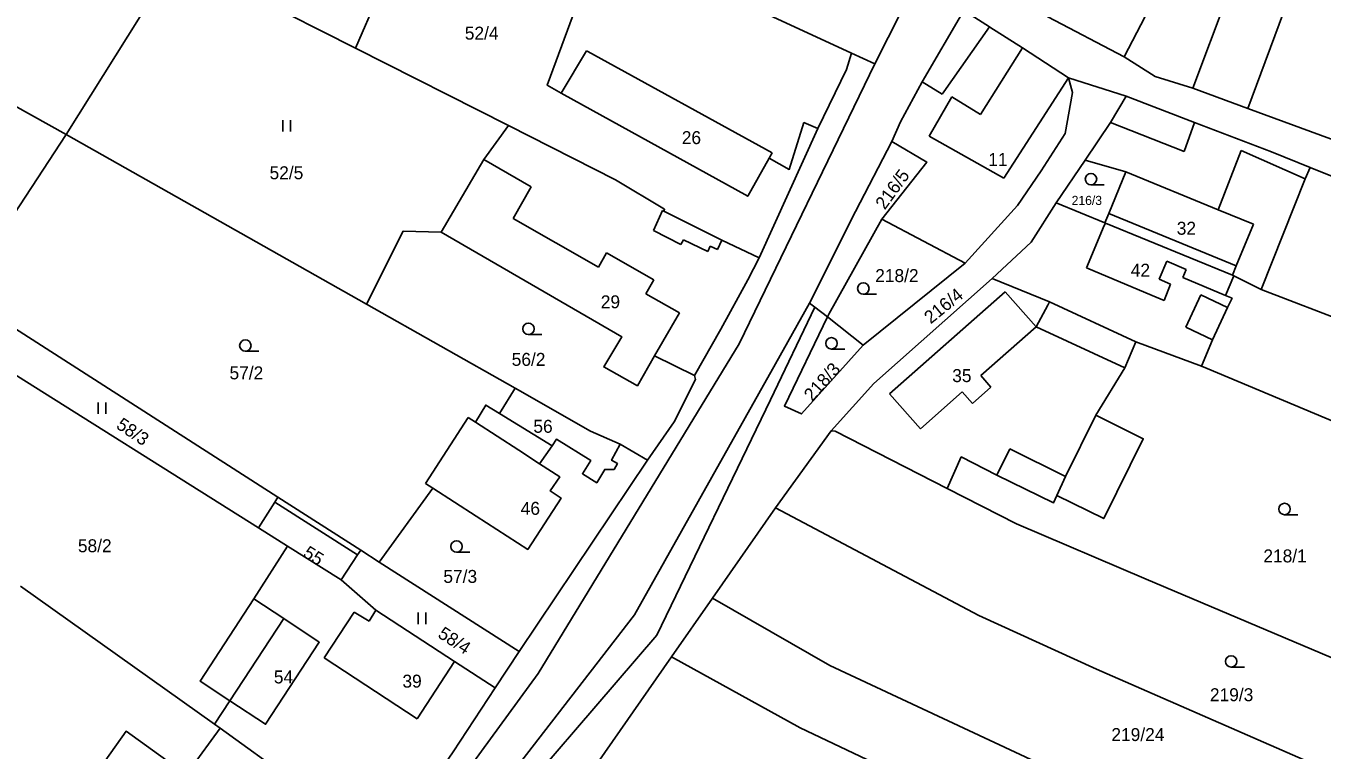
# Model space of a CAD drawing. Extents: x -746176 to -739709, y -1128407 to -1124482.
# Drawn here: x -743087.7 to -742917.8, y -1127669.6 to -1127574.6 of the extents above; entities that cross this region are included whole.
import ezdxf

# ---------------------------------------------------------------- set-up
doc = ezdxf.new("R2010")
doc.units = 0
for name, color, linetype in [('Hranice parcel', 7, 'Continuous'), ('Parcelní čísla', 7, 'Continuous'), ('Vnitřní kresba', 7, 'Continuous'), ('Značky kultur', 7, 'Continuous')]:
    doc.layers.add(name, color=color, linetype=linetype)

msp = doc.modelspace()

# ---------------------------------------------------------------- linework, layer by layer
at = {"layer": 'Hranice parcel'}
for p, q in [((-743082.43, -1127588.87), (-743239.89, -1127501.37)), ((-743029.41, -1127542.64), (-743044.5, -1127577.53)), ((-743082.43, -1127588.87), (-743067.95, -1127565.66)), ((-743067.95, -1127565.66), (-743044.5, -1127577.53)), ((-742979.47, -1127578.16), (-743001.38, -1127568.05)), ((-743044.5, -1127577.53), (-743024.44, -1127587.67)), ((-742943.48, -1127583.82), (-742951.01, -1127581.4)), ((-742985.72, -1127587.27), (-742983.9, -1127588.07)), ((-743096.19, -1127609.82), (-743082.43, -1127588.87)), ((-743082.43, -1127588.87), (-743043.08, -1127611.1)), ((-742991.6, -1127605.04), (-742983.9, -1127588.07)), ((-742952.62, -1127597.82), (-742948.85, -1127592.21)), ((-742919.33, -1127593.19), (-742889.07, -1127605.41)), ((-742946.24, -1127600.44), (-742952.62, -1127597.82)), ((-742982.46, -1127612.4), (-742975.48, -1127599.94)), ((-742975.48, -1127599.94), (-742964.56, -1127605.74)), ((-742964.56, -1127605.74), (-742977.94, -1127616.47)), ((-742925.74, -1127609.17), (-742929.36, -1127607.37)), ((-742892.31, -1127622.04), (-742925.74, -1127609.17)), ((-743096.19, -1127609.82), (-743054.68, -1127636.42)), ((-743043.08, -1127611.1), (-743023.57, -1127622.12)), ((-742982.64, -1127612.78), (-742984.29, -1127611.5)), ((-742982.64, -1127612.78), (-742982.46, -1127612.4)), ((-742977.94, -1127616.47), (-742982.64, -1127612.78)), ((-743057.24, -1127640.46), (-743099.02, -1127614.17)), ((-742933.59, -1127619.25), (-742942.21, -1127616.04)), ((-743023.57, -1127622.12), (-743025.65, -1127625.44)), ((-743029.73, -1127625.98), (-743035.35, -1127634.62)), ((-743018.73, -1127629.7), (-743025.65, -1127625.44)), ((-742989.43, -1127637.82), (-742982.16, -1127627.73)), ((-743009.79, -1127629.49), (-743006.21, -1127631.58)), ((-743006.21, -1127631.58), (-743023.07, -1127656.68)), ((-743035.35, -1127634.62), (-743034.37, -1127635.25)), ((-743043.83, -1127643.37), (-743054.68, -1127636.42)), ((-743041.39, -1127644.94), (-743034.37, -1127635.25)), ((-742997.69, -1127649.67), (-742989.43, -1127637.82)), ((-743057.24, -1127640.46), (-743053.43, -1127642.86)), ((-743053.43, -1127642.86), (-743057.84, -1127649.75)), ((-743046.41, -1127647.29), (-743053.43, -1127642.86)), ((-743043.83, -1127643.37), (-743041.39, -1127644.94)), ((-743041.39, -1127644.94), (-743023.07, -1127656.68)), ((-743062.98, -1127666.21), (-743088.43, -1127648.09)), ((-743003.07, -1127657.38), (-742997.69, -1127649.67)), ((-743023.07, -1127656.68), (-743026.2, -1127661.44)), ((-743013.81, -1127672.8), (-743003.07, -1127657.38)), ((-743060.97, -1127663.13), (-743062.98, -1127666.21)), ((-743062.24, -1127666.73), (-743062.98, -1127666.21)), ((-743045.29, -1127678.95), (-743062.24, -1127666.73))]:
    msp.add_line(p, q, dxfattribs=at)
for points in [[(-742927.53, -1127585.44), (-742922.25, -1127571.32), (-742918.6, -1127561.55)], [(-743009.74, -1127564.2), (-743012.24, -1127563.05), (-743019.38, -1127582.4), (-743017.56, -1127583.41), (-742993.08, -1127596.96), (-742990.26, -1127591.96)], [(-742967.51, -1127562.65), (-742971.19, -1127569.17), (-742976.43, -1127579.56), (-742979.47, -1127578.16)], [(-742927.53, -1127585.44), (-742934.7, -1127582.76), (-742939.64, -1127581.23), (-742943.72, -1127578.66), (-742953.72, -1127573.43), (-742957.84, -1127570.04), (-742958.76, -1127567.42), (-742958.43, -1127564.08)], [(-742964.75, -1127572.6), (-742970.21, -1127581.92), (-742973.05, -1127587.2), (-742974.2, -1127589.77)], [(-742951.01, -1127581.4), (-742957.06, -1127577.5), (-742961.32, -1127574.78), (-742961.39, -1127574.71), (-742964.75, -1127572.6)], [(-742983.9, -1127588.07), (-742980.12, -1127580.33), (-742979.47, -1127578.16)], [(-742964.56, -1127605.74), (-742957.73, -1127598.16), (-742954.62, -1127593.61), (-742951.47, -1127588.73), (-742950.51, -1127583.33), (-742951.01, -1127581.4)], [(-742948.85, -1127592.21), (-742945.53, -1127587.26), (-742943.48, -1127583.82)], [(-742943.48, -1127583.82), (-742934.51, -1127587.27), (-742924.42, -1127591.13), (-742919.33, -1127593.19)], [(-742885.79, -1127600.64), (-742896.8, -1127596.74), (-742927.53, -1127585.44)], [(-742990.26, -1127591.96), (-742987.63, -1127593.44), (-742985.72, -1127587.27)], [(-743024.44, -1127587.67), (-743027.7, -1127592.11), (-743033.28, -1127601.65)], [(-743024.44, -1127587.67), (-743010.42, -1127594.79), (-743003.98, -1127598.66), (-743004.09, -1127598.89), (-742996.47, -1127602.7), (-742991.6, -1127605.04)], [(-742984.29, -1127611.5), (-742984.97, -1127610.98), (-742978.95, -1127598.97), (-742974.2, -1127589.77)], [(-742974.2, -1127589.77), (-742969.61, -1127592.47), (-742975.48, -1127599.94)], [(-742948.85, -1127592.21), (-742943.5, -1127593.76), (-742945.74, -1127599.22), (-742946.24, -1127600.44)], [(-742925.74, -1127609.17), (-742920.01, -1127594.66), (-742919.33, -1127593.19)], [(-742961.05, -1127607.72), (-742955.92, -1127602.99), (-742952.62, -1127597.82)], [(-742946.24, -1127600.44), (-742946.19, -1127600.46), (-742929.52, -1127607.31), (-742929.36, -1127607.37)], [(-743043.08, -1127611.1), (-743038.28, -1127601.54), (-743033.28, -1127601.65)], [(-743033.28, -1127601.65), (-743009.6, -1127615.39), (-743011.96, -1127619.34), (-743007.55, -1127621.8), (-743005.29, -1127617.87), (-743000.05, -1127620.45)], [(-742991.6, -1127605.04), (-742993.07, -1127607.9), (-742996.62, -1127614.4), (-743000.05, -1127620.45)], [(-742982.16, -1127627.73), (-742976.55, -1127621.53), (-742961.05, -1127607.72)], [(-742942.21, -1127616.04), (-742953.51, -1127610.79), (-742961.05, -1127607.72)], [(-742929.36, -1127607.37), (-742930.45, -1127609.97), (-742929.58, -1127610.33), (-742930.16, -1127611.56), (-742932.13, -1127615.77), (-742933.59, -1127619.25)], [(-742984.29, -1127611.5), (-742990.11, -1127623.65), (-743005.02, -1127654.54), (-743028.72, -1127682.17), (-743035.1, -1127691.53)], [(-742977.94, -1127616.47), (-742986.05, -1127625.51), (-742988.28, -1127624.48), (-742982.64, -1127612.78)], [(-742942.21, -1127616.04), (-742943.64, -1127619.44), (-742947.46, -1127625.69), (-742941.23, -1127628.77), (-742946.4, -1127639.24), (-742952.54, -1127636.21), (-742953.01, -1127637.17), (-742960.41, -1127633.52), (-742965.09, -1127631.14), (-742966.93, -1127635.29)], [(-742933.59, -1127619.25), (-742932.84, -1127619.53), (-742895.2, -1127635.33)], [(-743000.05, -1127620.45), (-742999.93, -1127620.98), (-743002.72, -1127626.56), (-743006.21, -1127631.58)], [(-743009.79, -1127629.49), (-743013.72, -1127627.78), (-743023.57, -1127622.12)], [(-743025.65, -1127625.44), (-743027.43, -1127624.34), (-743028.79, -1127626.59), (-743029.73, -1127625.98)], [(-742966.93, -1127635.29), (-742981.61, -1127627.78), (-742982.16, -1127627.73)], [(-743034.37, -1127635.25), (-743028.68, -1127638.9), (-743021.92, -1127643.29), (-743017.55, -1127636.55), (-743018.97, -1127635.6), (-743017.73, -1127633.76), (-743020.38, -1127632.04), (-743018.73, -1127629.7)], [(-743018.73, -1127629.7), (-743018.16, -1127628.82), (-743013.67, -1127631.63), (-743014.75, -1127633.35), (-743012.87, -1127634.54), (-743011.82, -1127632.78), (-743010.61, -1127632.81), (-743010.16, -1127632.03), (-743010.94, -1127631.59), (-743009.79, -1127629.49)], [(-743054.68, -1127636.42), (-743055.09, -1127637.08), (-743057.24, -1127640.46)], [(-742966.93, -1127635.29), (-742957.86, -1127639.93), (-742940.86, -1127647.2), (-742894.92, -1127666.66), (-742890.34, -1127668.53)], [(-742989.43, -1127637.82), (-742962.79, -1127651.94), (-742947.37, -1127659.01), (-742888.66, -1127684.65), (-742875.08, -1127689.31), (-742869.86, -1127690.69)], [(-743046.41, -1127647.29), (-743044.24, -1127643.99), (-743043.83, -1127643.37)], [(-743026.2, -1127661.44), (-743031.54, -1127657.97), (-743041.85, -1127651.26), (-743046.41, -1127647.29)], [(-743057.84, -1127649.75), (-743064.89, -1127660.55), (-743060.97, -1127663.13)], [(-743057.84, -1127649.75), (-743053.93, -1127652.35), (-743049.27, -1127655.45), (-743056.31, -1127666.21), (-743060.97, -1127663.13)], [(-742884.93, -1127701.69), (-742931.01, -1127682.52), (-742982.33, -1127658.51), (-742997.69, -1127649.67)], [(-742892.82, -1127707.45), (-742959.07, -1127679.57), (-742986.2, -1127666.67), (-743003.07, -1127657.38)], [(-743026.2, -1127661.44), (-743031.72, -1127669.85), (-743034.56, -1127673.98), (-743037.58, -1127678), (-743040.96, -1127682.5)], [(-743050.26, -1127695.79), (-743074.95, -1127680.59), (-743077.21, -1127683.74), (-743083.3, -1127679.41), (-743074.6, -1127667.14), (-743068.46, -1127671.55), (-743066.13, -1127672.07), (-743062.24, -1127666.73)]]:
    msp.add_lwpolyline(points, dxfattribs=at)
at = {"layer": 'Vnitřní kresba'}
for p, q in [((-742934.7, -1127582.76), (-742929.42, -1127568.64)), ((-742943.72, -1127578.66), (-742940.95, -1127573.36)), ((-742967.39, -1127583.25), (-742961.39, -1127574.71)), ((-743017.56, -1127583.41), (-743014.23, -1127577.87)), ((-743014.23, -1127577.87), (-743014.05, -1127577.97)), ((-743014.05, -1127577.97), (-742989.86, -1127591.25)), ((-742962.56, -1127586.21), (-742957.06, -1127577.5)), ((-742994.19, -1127616.32), (-742976.43, -1127579.56)), ((-742970.21, -1127581.92), (-742967.6, -1127583.54)), ((-742959.5, -1127594.6), (-742951.01, -1127581.4)), ((-742969.28, -1127589.06), (-742966.31, -1127583.91)), ((-742967.6, -1127583.54), (-742967.39, -1127583.25)), ((-742966.31, -1127583.91), (-742962.56, -1127586.21)), ((-742945.53, -1127587.26), (-742935.86, -1127591.09)), ((-742935.86, -1127591.09), (-742934.51, -1127587.27)), ((-742969.28, -1127589.06), (-742959.5, -1127594.6)), ((-742931.41, -1127598.72), (-742928.39, -1127590.97)), ((-742928.39, -1127590.97), (-742920.01, -1127594.66)), ((-743027.7, -1127592.11), (-743021.5, -1127595.7)), ((-742990.26, -1127591.96), (-742989.86, -1127591.25)), ((-742943.5, -1127593.76), (-742931.41, -1127598.72)), ((-743023.86, -1127599.87), (-743021.5, -1127595.7)), ((-743005.46, -1127601.43), (-743004.27, -1127598.8)), ((-743004.27, -1127598.8), (-743004.09, -1127598.89)), ((-742945.74, -1127599.22), (-742929.02, -1127606.08)), ((-742931.41, -1127598.72), (-742926.78, -1127600.62)), ((-743023.86, -1127599.87), (-743012.63, -1127606.25)), ((-742948.66, -1127606.36), (-742946.33, -1127600.8)), ((-742946.33, -1127600.8), (-742946.19, -1127600.46)), ((-742929.02, -1127606.08), (-742926.78, -1127600.62)), ((-743005.46, -1127601.43), (-743001.84, -1127603.28)), ((-743001.84, -1127603.28), (-743001.52, -1127602.66)), ((-743001.52, -1127602.66), (-742998.3, -1127604.18)), ((-742997.05, -1127603.92), (-742996.47, -1127602.7)), ((-743012.63, -1127606.25), (-743011.59, -1127604.36)), ((-743011.59, -1127604.36), (-743005.38, -1127607.91)), ((-742998.3, -1127604.18), (-742997.99, -1127603.52)), ((-742997.99, -1127603.52), (-742997.05, -1127603.92)), ((-742939.14, -1127607.84), (-742938.15, -1127605.48)), ((-742938.15, -1127605.48), (-742935.61, -1127606.55)), ((-742929.52, -1127607.31), (-742929.02, -1127606.08)), ((-743006.43, -1127609.77), (-743005.38, -1127607.91)), ((-742948.66, -1127606.36), (-742940.04, -1127609.97)), ((-742939.14, -1127607.84), (-742937.66, -1127608.47)), ((-742936.05, -1127607.62), (-742935.61, -1127606.55)), ((-742936.05, -1127607.62), (-742930.45, -1127609.97)), ((-742974.48, -1127622.89), (-742959.34, -1127609.47)), ((-742959.34, -1127609.47), (-742955.28, -1127614.06)), ((-742938.46, -1127610.63), (-742937.66, -1127608.47)), ((-743006.43, -1127609.77), (-743002.05, -1127612.26)), ((-742989.42, -1127618.93), (-742984.97, -1127610.98)), ((-742955.28, -1127614.06), (-742953.75, -1127611.23)), ((-742953.75, -1127611.23), (-742953.51, -1127610.79)), ((-742940.04, -1127609.97), (-742938.46, -1127610.63)), ((-742935.66, -1127614.11), (-742933.69, -1127609.9)), ((-742933.69, -1127609.9), (-742930.16, -1127611.56)), ((-743005.29, -1127617.87), (-743002.05, -1127612.26)), ((-742962.53, -1127620.48), (-742955.28, -1127614.06)), ((-742955.28, -1127614.06), (-742943.64, -1127619.44)), ((-742935.66, -1127614.11), (-742932.13, -1127615.77)), ((-743020.57, -1127659.55), (-742994.19, -1127616.32)), ((-743007.93, -1127651.85), (-742989.42, -1127618.93)), ((-742962.53, -1127620.48), (-742961.2, -1127621.98)), ((-742974.48, -1127622.89), (-742970.42, -1127627.47)), ((-742970.42, -1127627.47), (-742964.95, -1127622.62)), ((-742964.95, -1127622.62), (-742963.62, -1127624.12)), ((-742963.62, -1127624.12), (-742961.2, -1127621.98)), ((-743028.79, -1127626.59), (-743023.09, -1127630.28)), ((-742951.41, -1127633.7), (-742947.46, -1127625.69)), ((-743023.09, -1127630.28), (-743020.38, -1127632.04)), ((-742960.41, -1127633.52), (-742958.72, -1127630.09)), ((-742958.72, -1127630.09), (-742951.41, -1127633.7)), ((-742952.54, -1127636.21), (-742951.41, -1127633.7)), ((-743055.09, -1127637.08), (-743044.24, -1127643.99)), ((-743048.61, -1127657.52), (-743044.69, -1127651.52)), ((-743044.69, -1127651.52), (-743042.7, -1127652.7)), ((-743042.7, -1127652.7), (-743041.85, -1127651.26)), ((-743030.45, -1127680.95), (-743007.93, -1127651.85)), ((-743060.97, -1127663.13), (-743053.93, -1127652.35)), ((-743048.61, -1127657.52), (-743036.42, -1127665.5)), ((-743036.42, -1127665.5), (-743031.54, -1127657.97)), ((-743038.55, -1127684.18), (-743020.57, -1127659.55))]:
    msp.add_line(p, q, dxfattribs=at)
at = {"layer": 'Značky kultur'}
for p, q in [((-743054.05, -1127588.47), (-743054.05, -1127586.97)), ((-743053.05, -1127588.47), (-743053.05, -1127586.97)), ((-742948.08, -1127595.45), (-742946.33, -1127595.45)), ((-742977.93, -1127609.8), (-742976.18, -1127609.8)), ((-743021.84, -1127615.09), (-743020.09, -1127615.09)), ((-743058.95, -1127617.29), (-743057.2, -1127617.29)), ((-742982.11, -1127617), (-742980.36, -1127617)), ((-743078.24, -1127625.49), (-743078.24, -1127623.99)), ((-743077.24, -1127625.49), (-743077.24, -1127623.99)), ((-742922.69, -1127638.73), (-742920.94, -1127638.73)), ((-743031.26, -1127643.64), (-743029.51, -1127643.64)), ((-743036.31, -1127653.07), (-743036.31, -1127651.57)), ((-743035.31, -1127653.07), (-743035.31, -1127651.57)), ((-742929.7, -1127658.72), (-742927.95, -1127658.72))]:
    msp.add_line(p, q, dxfattribs=at)
for centre in [(-742948.08, -1127594.7), (-742977.93, -1127609.05), (-743021.84, -1127614.34), (-743058.95, -1127616.54), (-742982.11, -1127616.25), (-742922.69, -1127637.98), (-743031.26, -1127642.89), (-742929.7, -1127657.97)]:
    msp.add_circle(centre, 0.75, dxfattribs=at)

# ---------------------------------------------------------------- texts
at = {"layer": 'Parcelní čísla'}
for s, height, p in [('52/4', 1.7, (-743030.18, -1127576.4)), ('26', 1.7, (-743001.73, -1127590.11)), ('11', 1.7, (-742961.55, -1127592.98)), ('52/5', 1.7, (-743055.78, -1127594.72)), ('216/3', 1.19, (-742950.61, -1127598.09)), ('32', 1.7, (-742936.83, -1127602)), ('42', 1.7, (-742942.86, -1127607.5)), ('218/2', 1.7, (-742976.37, -1127608.21)), ('29', 1.7, (-743012.35, -1127611.65)), ('56/2', 1.7, (-743024.03, -1127619.2)), ('57/2', 1.7, (-743061.03, -1127620.97)), ('35', 1.7, (-742966.27, -1127621.33)), ('56', 1.7, (-743021.19, -1127627.98)), ('46', 1.7, (-743022.85, -1127638.74)), ('58/2', 1.7, (-743080.91, -1127643.65)), ('218/1', 1.7, (-742925.47, -1127644.98)), ('57/3', 1.7, (-743032.99, -1127647.67)), ('54', 1.7, (-743055.22, -1127660.86)), ('39', 1.7, (-743038.36, -1127661.41)), ('219/3', 1.7, (-742932.48, -1127663.19)), ('219/24', 1.7, (-742945.4, -1127668.42))]:
    msp.add_text(s, height=height, dxfattribs=at).set_placement(p)
for s, rotation, p in [('216/5', 54, (-742975.11, -1127598.82)), ('216/4', 39, (-742969.09, -1127613.77)), ('218/3', 48, (-742984.62, -1127623.96)), ('58/3', 326, (-743076.01, -1127627.29)), ('55', 328, (-743051.52, -1127644.15)), ('58/4', 327, (-743033.84, -1127654.73))]:
    msp.add_text(s, height=1.7, rotation=rotation, dxfattribs=at).set_placement(p)

doc.saveas('drawing.dxf')
